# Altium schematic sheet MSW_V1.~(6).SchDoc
size B; Organization: ORGANIZATION; Address1: ADDRESS 1; Address2: ADDRESS 2; Address3: ADDRESS 3; Address4: ADDRESS 4; Revision: -; SheetNumber: 1; SheetTotal: 1; ENG_APP_DATE: --/--/--; DSN_APP_DATE: --/--/--; CHK_APP_DATE: --/--/--
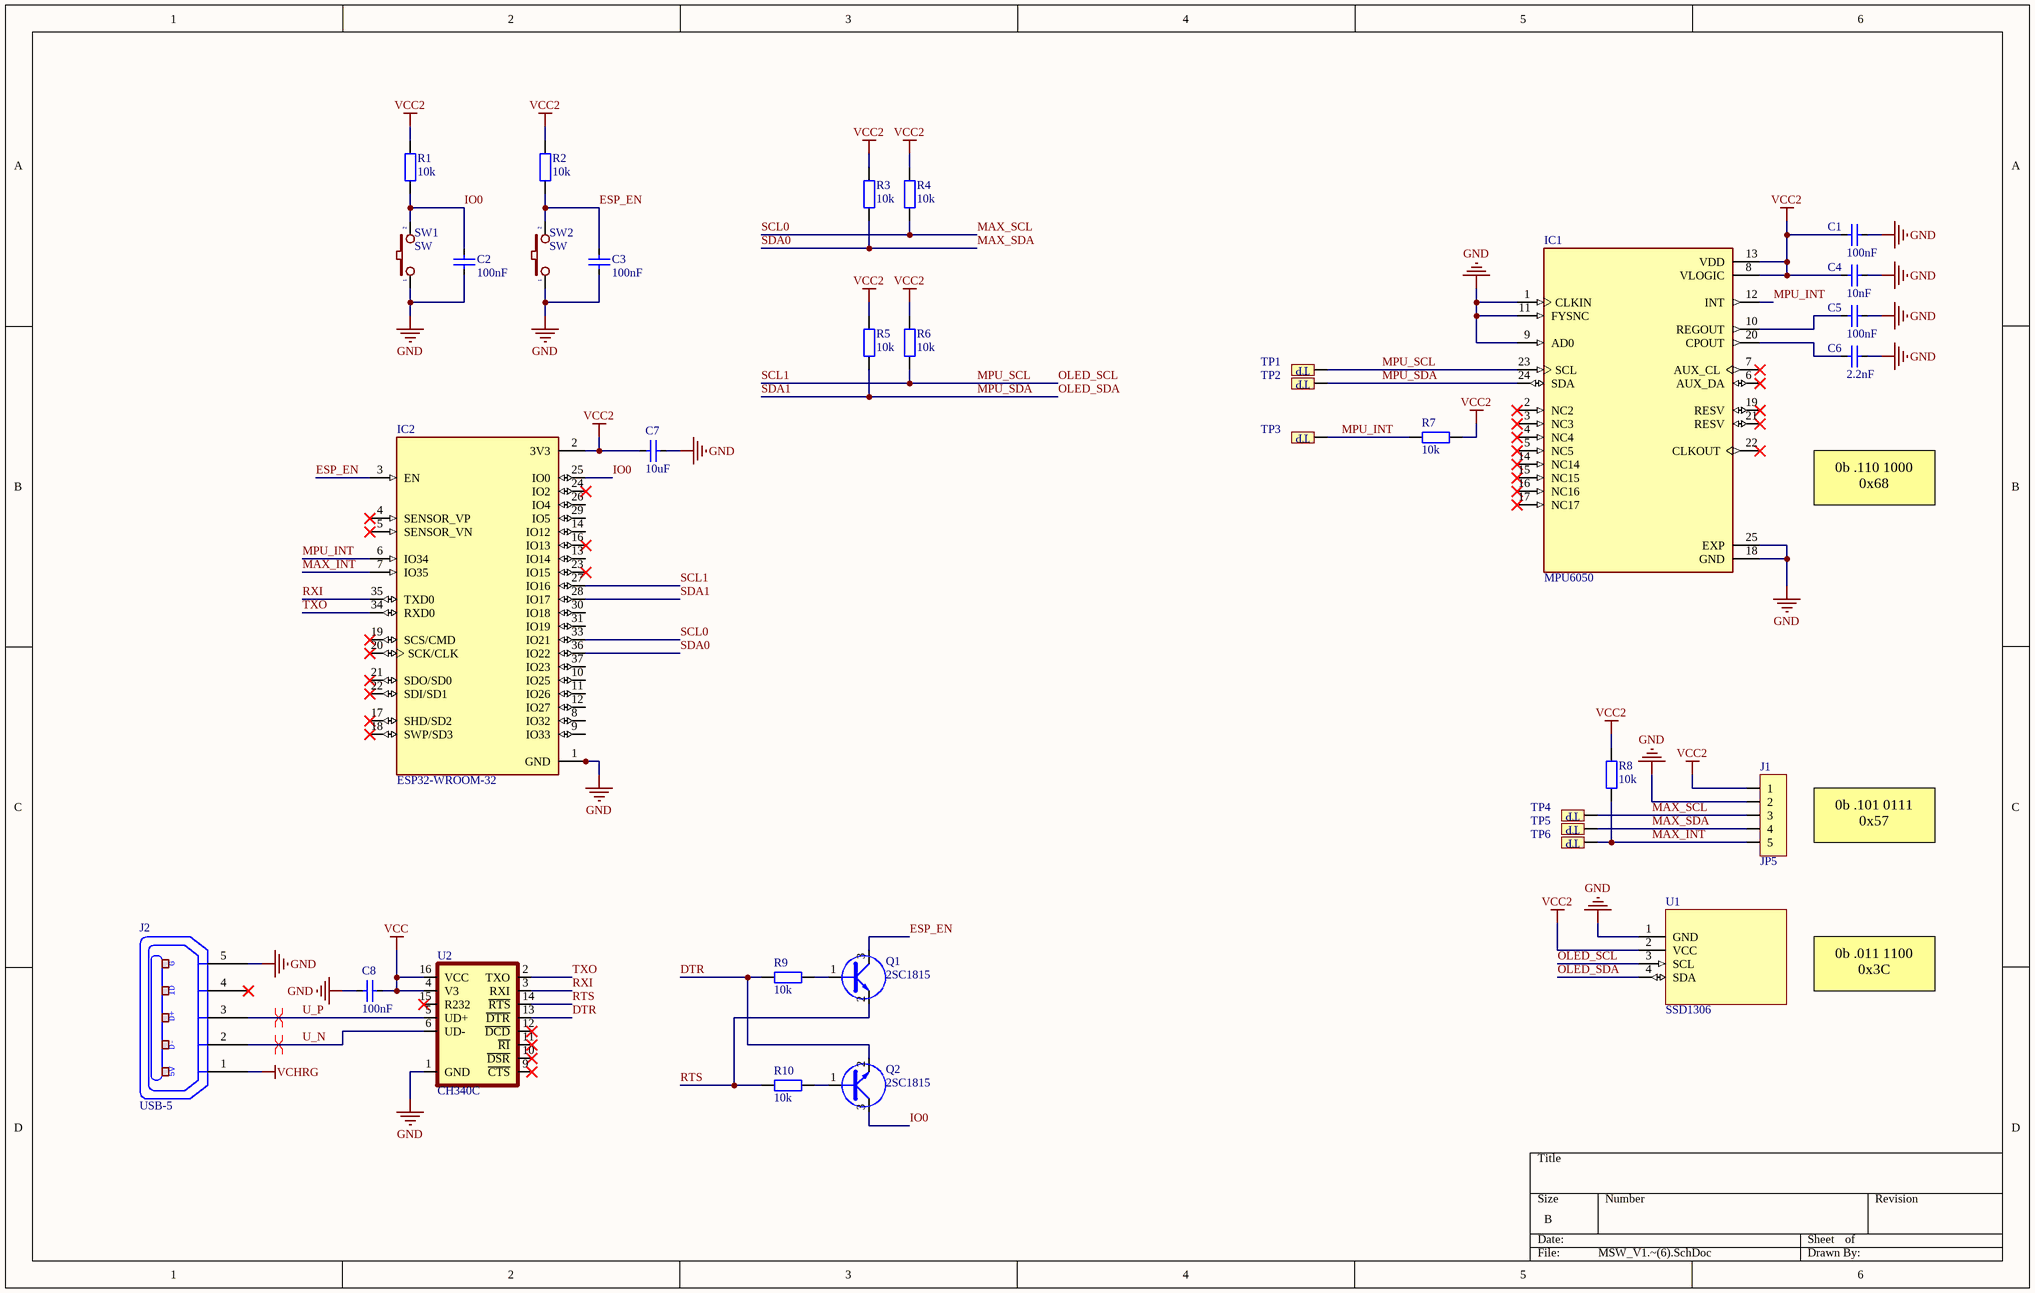
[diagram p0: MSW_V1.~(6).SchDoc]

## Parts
C1  100nF  [CAP_0603]
C2  100nF  [CAP_0603]
C3  100nF  [CAP_0603]
C4  10nF  [CAP_0603]
C5  100nF  [CAP_0603]
C6  2.2nF  [CAP_0603]
C7  10uF  [CAP_0603]
C8  100nF  [CAP_0603]
IC1  MPU6050  [QFN24]
IC2  ESP32-WROOM-32  [MODULE_ESP32-WROOM-32]
J1  JP5  [Header5 - TH - 1.25MM]
J2  USB-5  [USB-M1]
Q1  2SC1815  [SOT23D]
Q2  2SC1815  [SOT23D]
R1  10k  [RES-SMD-0603]
R2  10k  [RES-SMD-0603]
R3  10k  [RES-SMD-0603]
R4  10k  [RES-SMD-0603]
R5  10k  [RES-SMD-0603]
R6  10k  [RES-SMD-0603]
R7  10k  [RES-SMD-0603]
R8  10k  [RES-SMD-0603]
R9  10k  [RES-SMD-0603]
R10  10k  [RES-SMD-0603]
SW1  SW  [SW 3x2x4]
SW2  SW  [SW 3x2x4]
TP1  TP  [TP_SMD]  (value not drawn)
TP2  TP  [TP_SMD]  (value not drawn)
TP3  TP  [TP_SMD]  (value not drawn)
TP4  TP  [TP_SMD]  (value not drawn)
TP5  TP  [TP_SMD]  (value not drawn)
TP6  TP  [TP_SMD]  (value not drawn)
U1  SSD1306  [OLED 1.3 SSD1306 PRETTY NON POLE]
U2  CH340C  [SOP-16]

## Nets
GND: C1.1 C2.2 C3.2 C4.1 C5.1 C6.1 C7.2 C8.1 IC1.1(CLKIN) IC1.9(AD0) IC1.11(FYSNC) IC1.18(GND) IC1.25(EXP) IC2.1(GND) IC2.15(GND) IC2.38(GND) IC2.39_1(GND) IC2.39_2(GND) IC2.39_3(GND) IC2.39_4(GND) IC2.39_5(GND) IC2.39_6(GND) IC2.39_7(GND) IC2.39_8(GND) IC2.39_9(GND) IC2.39_10(GND) IC2.39_11(GND) IC2.39_12(GND) IC2.39_13(GND) IC2.39_14(GND) IC2.39_15(GND) IC2.39_16(GND) IC2.39_17(GND) IC2.39_18(GND) IC2.39_19(GND) IC2.39_20(GND) IC2.39_21(GND) J1.2 J2.5(P5) SW1.1 SW2.1 U1.1(GND) U2.1(GND)
VCC: C8.2 U2.4(V3) U2.16(VCC)
VCC2: C1.2 C4.2 C7.1 IC1.8(VLOGIC) IC1.13(VDD) IC2.2(3V3) J1.1 R1.2 R2.2 R3.2 R4.2 R5.2 R6.2 R7.1 R8.1 U1.2(VCC)
VCHRG: J2.1(P1)
DTR: Q2.2(E) R9.2 U2.13(~{DTR})
ESP_EN: C3.1 IC2.3(EN) Q1.3(C) R2.1 SW2.2
IO0: C2.1 IC2.25(IO0) Q2.3(C) R1.1 SW1.2
MAX_INT: IC2.7(IO35) J1.5 R8.2 TP6.1
MAX_SCL: IC2.33(IO21) J1.3 R4.1 TP4.1  [also labelled SCL0]
MAX_SDA: IC2.36(IO22) J1.4 R3.1 TP5.1  [also labelled SDA0]
MPU_INT: IC1.12(INT) IC2.6(IO34) R7.2 TP3.1
MPU_SCL: IC1.23(SCL) IC2.27(IO16) R6.1 TP1.1 U1.3(SCL)  [also labelled OLED_SCL, SCL1]
MPU_SDA: IC1.24(SDA) IC2.28(IO17) R5.1 TP2.1 U1.4(SDA)  [also labelled OLED_SDA, SDA1]
RTS: Q1.2(E) R10.2 U2.14(~{RTS})
RXI: IC2.35(TXD0) U2.3(RXI)
TXO: IC2.34(RXD0) U2.2(TXO)
U_N: J2.2(P2) U2.6(UD-)
U_P: J2.3(P3) U2.5(UD+)
NetC5_2: C5.2 IC1.10(REGOUT)
NetC6_2: C6.2 IC1.20(CPOUT)
NetQ1_1: Q1.1(B) R9.1
NetQ2_1: Q2.1(B) R10.1

Not connected (* = marked no-connect by the designer): IC1 2(NC2)* 3(NC3)* 4(NC4)* 5(NC5)* 6(AUX_DA)* 7(AUX_CL)* 14(NC14)* 15(NC15)* 16(NC16)* 17(NC17)* 19(RESV)* 21(RESV)* 22(CLKOUT)*; IC2 4(SENSOR_VP)* 5(SENSOR_VN)* 8(IO32) 9(IO33) 10(IO25) 11(IO26) 12(IO27) 13(IO14) 14(IO12) 16(IO13)* 17(SHD/SD2)* 18(SWP/SD3)* 19(SCS/CMD)* 20(SCK/CLK)* 21(SDO/SD0)* 22(SDI/SD1)* 23(IO15)* 24(IO2)* 26(IO4) 29(IO5) 30(IO18) 31(IO19) 37(IO23); J2 4(P4)*; U2 9(~{CTS})* 10(~{DSR})* 11(~{RI})* 12(~{DCD})* 15(R232)*

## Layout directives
differential pair: U_N, U_P

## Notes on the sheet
- 0b .110 1000
  0x68
- 0b .101 0111
  0x57
- 0b .011 1100
  0x3C

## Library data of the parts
C1-C8 = CapSMD: Capacitor; Value: 33p
IC1 = MPU6050_Chip: 3-axis gyroscope, 3-axis accelerometer
IC2 = ESP32-WROOM-32: Bluetooth, WiFi Transceiver Module 2.4GHz ~ 2.5GHz Surface Mount; MF: Espressif Systems
J1 = JP5x1: WR-PHD 2.54 mm Angled Socket Header; Manufacturer: W¨¹rth Elektronik eiSos GmbH; partNo: 613005143121; ComponentLink1 Description: Manufacturer; ComponentLink2 Description: Datasheet; NoPins: 05
J2 = USB-5: Manufacturer: FCI; Manufacturer Part Number: 10118193-0001LF; Connector Type: USB - micro B; Number of Contacts: 5; Gender: Receptacle; Specifications: USB 2.0; .Creator: MM; .Checked PCB: RF
Q1 Q2 = C1815: NPN 600mW, ECB; Value: C1815
R1-R10 = Resistor - SMD: Resistor SMD; Manufacturer: Generic Components; Class: Passive
SW1 SW2 = SW2: Switch button 2 pin; Value: SW chip 2 pin
TP1-TP6 = TP: CONNECT 1
U1 = OLED 1.3 SSD1306: OLED Display 1.3" SSD1306
U2 = CH340C: USB to serial chip CH340; MF: WCH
